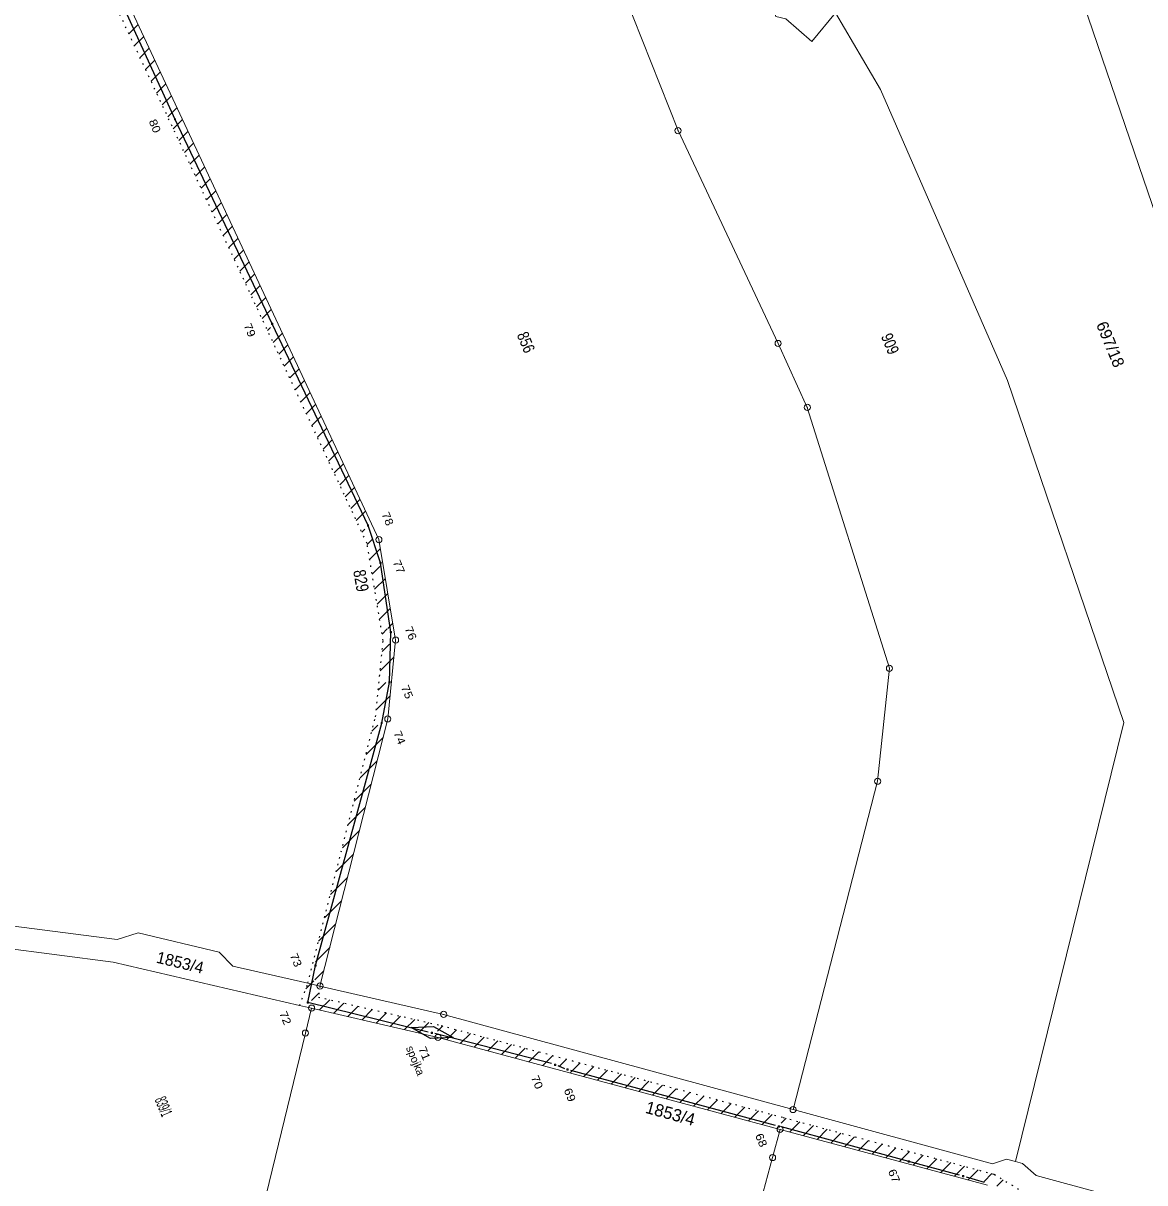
# Model space of a CAD drawing. Extents: x -687415 to -686486, y -959539 to -958099.
# Drawn here: x -686991 to -686717.8, y -959271.3 to -958988.8 of the extents above; entities that cross this region are included whole.
import ezdxf
from ezdxf.enums import TextEntityAlignment as Align

# ---------------------------------------------------------------- set-up
doc = ezdxf.new("R2010")
doc.units = 0
doc.header["$LTSCALE"] = 1.1
doc.linetypes.add('DOTTED', pattern=[1.5, 0.3, -1.2])
for name, color, linetype, lineweight in [('1', 7, 'Continuous', 13), ('2', 7, 'Continuous', 25), ('3', 7, 'Continuous', 13)]:
    doc.layers.add(name, color=color, linetype=linetype, lineweight=lineweight)

msp = doc.modelspace()

# ---------------------------------------------------------------- linework, layer by layer
at = {"layer": '1', "linetype": 'DOTTED', "lineweight": 25}
for p, q in [((-686907.24, -959115.56), (-686968.42, -958984.64)), ((-686921.64, -959222.72), (-686905.15, -959157.8)), ((-686923.68, -959228.09), (-686921.64, -959222.72))]:
    msp.add_line(p, q, dxfattribs=at)
at = {"layer": '1'}
for p, q in [((-686923.68, -959228.09), (-686920.76, -959228.77)), ((-686806.61, -959258.31), (-686756.11, -959271.89))]:
    msp.add_line(p, q, dxfattribs=at)
for points in [[(-686815.11, -958834.64), (-686805.51, -958854.31), (-686782.73, -958855.23), (-686777.25, -958855.45), (-686769.17, -958878.16), (-686758.67, -958907.68), (-686744.98, -958948.05), (-686719.22, -959023.5), (-686699.65, -959080.73), (-686683.05, -959115.22), (-686652.59, -959178.05), (-686618.25, -959249.24), (-686597.25, -959289.88), (-686633.86, -959286.61), (-686711.27, -959277.22), (-686727.83, -959274.04), (-686744.23, -959269.58), (-686747.57, -959266.6), (-686749.25, -959266.14)], [(-686890.94, -958843.77), (-686860.7, -958840.13), (-686859.87, -958843.5), (-686839.25, -958887.41), (-686807.64, -958987.21), (-686805.21, -958987.76), (-686798.91, -958993.27), (-686793.12, -958986.35), (-686782.13, -959004.96), (-686751.25, -959075.9), (-686722.86, -959159.17), (-686749.25, -959266.14)], [(-686970.07, -958962.96), (-686957.75, -958981.41), (-686965.66, -958983.46), (-686904.35, -959114.65)], [(-686844.58, -958981.76), (-686831.48, -959015.02), (-686807.1, -959066.85), (-686799.98, -959082.42), (-686779.98, -959145.99)], [(-686904.35, -959114.65), (-686900.3, -959139.13), (-686902.2, -959158.32), (-686918.72, -959223.39)], [(-686779.98, -959145.99), (-686782.85, -959173.5), (-686803.44, -959253.47)], [(-686921.64, -959222.72), (-686939.9, -959218.53), (-686943.3, -959215.1), (-686962.99, -959210.39), (-686968.12, -959212.05), (-686996.45, -959208.38), (-687006.2, -959208.87)], [(-687007.06, -959214.49), (-686996.53, -959213.97), (-686969.1, -959217.56), (-686923.68, -959228.09)], [(-686803.44, -959253.47), (-686888.58, -959230.3), (-686918.72, -959223.39)], [(-686920.76, -959228.77), (-686922.24, -959234.86), (-686986.17, -959497.52)], [(-686920.76, -959228.77), (-686889.94, -959235.91), (-686806.61, -959258.31), (-686808.46, -959265.16), (-686838.63, -959377.05), (-686887.06, -959538.48)], [(-686749.25, -959266.14), (-686751.43, -959265.55), (-686754.85, -959266.69), (-686803.44, -959253.47)]]:
    msp.add_lwpolyline(points, dxfattribs=at)
for points in [[(-686954.18, -959012.42), (-686954.18, -959012.12), (-686953.88, -959012.12), (-686953.88, -959012.42)], [(-686930.48, -959062.22), (-686930.48, -959061.92), (-686930.18, -959061.92), (-686930.18, -959062.22)], [(-686907.16, -959111.38), (-686907.16, -959111.08), (-686906.86, -959111.08), (-686906.86, -959111.38)], [(-686904.12, -959120.46), (-686904.12, -959120.16), (-686903.82, -959120.16), (-686903.82, -959120.46)], [(-686901.61, -959137.32), (-686901.61, -959137.02), (-686901.31, -959137.02), (-686901.31, -959137.32)], [(-686901.95, -959149.5), (-686901.95, -959149.2), (-686901.65, -959149.2), (-686901.65, -959149.5)], [(-686903.83, -959159.47), (-686903.83, -959159.17), (-686903.53, -959159.17), (-686903.53, -959159.47)], [(-686919.94, -959218.54), (-686919.94, -959218.24), (-686919.64, -959218.24), (-686919.64, -959218.54)], [(-686921.81, -959227.54), (-686921.81, -959227.24), (-686921.51, -959227.24), (-686921.51, -959227.54)], [(-686891.632, -959234.958), (-686891.632, -959234.658), (-686891.332, -959234.658), (-686891.332, -959234.958)], [(-686861.56, -959242.71), (-686861.56, -959242.41), (-686861.26, -959242.41), (-686861.26, -959242.71)], [(-686858.533, -959243.87), (-686858.533, -959243.57), (-686858.233, -959243.57), (-686858.233, -959243.87)], [(-686807.076, -959257.739), (-686807.076, -959257.439), (-686806.776, -959257.439), (-686806.776, -959257.739)], [(-686775.41, -959266.27), (-686775.41, -959265.97), (-686775.11, -959265.97), (-686775.11, -959266.27)], [(-686762.138, -959269.85), (-686762.138, -959269.55), (-686761.838, -959269.55), (-686761.838, -959269.85)]]:
    msp.add_lwpolyline(points, close=True, dxfattribs=at)
at = {"layer": '1', "linetype": 'DOTTED', "lineweight": 25}
for points in [[(-686905.15, -959157.8), (-686903.33, -959139.21), (-686907.24, -959115.56)], [(-686918.72, -959223.39), (-686919.1, -959226.08), (-686889.21, -959233), (-686805.83, -959255.41), (-686754.43, -959269.25), (-686745.48, -959274.75)]]:
    msp.add_lwpolyline(points, dxfattribs=at)
at = {"layer": '1', "lineweight": 25}
msp.add_lwpolyline([(-686896.505, -959233.514), (-686891.049, -959233.281), (-686886.295, -959235.965), (-686891.75, -959236.198)], close=True, dxfattribs=at)
at = {"layer": '1'}
for centre, radius in [((-686831.48, -959015.02), 0.75), ((-686831.48, -959015.02), 0.015), ((-686807.1, -959066.85), 0.75), ((-686807.1, -959066.85), 0.015), ((-686799.98, -959082.42), 0.75), ((-686799.98, -959082.42), 0.015), ((-686904.35, -959114.65), 0.75), ((-686904.35, -959114.65), 0.015), ((-686900.3, -959139.13), 0.75), ((-686900.3, -959139.13), 0.015), ((-686779.98, -959145.99), 0.75), ((-686779.98, -959145.99), 0.015), ((-686902.2, -959158.32), 0.75), ((-686902.2, -959158.32), 0.015), ((-686782.85, -959173.5), 0.75), ((-686782.85, -959173.5), 0.015), ((-686918.72, -959223.39), 0.75), ((-686918.72, -959223.39), 0.015), ((-686920.76, -959228.77), 0.75), ((-686920.76, -959228.77), 0.015), ((-686888.58, -959230.3), 0.75), ((-686888.58, -959230.3), 0.015), ((-686922.24, -959234.86), 0.75), ((-686922.24, -959234.86), 0.015), ((-686889.94, -959235.91), 0.75), ((-686889.94, -959235.91), 0.015), ((-686803.44, -959253.47), 0.75), ((-686803.44, -959253.47), 0.015), ((-686806.61, -959258.31), 0.75), ((-686806.61, -959258.31), 0.015), ((-686808.46, -959265.16), 0.75), ((-686808.46, -959265.16), 0.015)]:
    msp.add_circle(centre, radius, dxfattribs=at)
at = {"layer": '2', "lineweight": 13}
msp.add_line((-686918.72, -959223.39), (-686921.64, -959222.72), dxfattribs=at)
at = {"layer": '2'}
for p, q in [((-686862.295, -959242.281), (-686890.719, -959234.991)), ((-686859.066, -959243.535), (-686860.671, -959242.807)), ((-686807.704, -959257.358), (-686857.599, -959243.941)), ((-686756.823, -959271.237), (-686761.177, -959269.978))]:
    msp.add_line(p, q, dxfattribs=at)
for points in [[(-686892.32, -959234.647), (-686921.66, -959227.39), (-686919.79, -959218.39), (-686903.68, -959159.32), (-686901.8, -959149.35), (-686901.46, -959137.17), (-686903.97, -959120.31), (-686907.01, -959111.23), (-686930.33, -959062.07), (-686954.03, -959012.27), (-686967.47, -958982.75), (-686974.24, -958965.45), (-686981.42, -958939.69), (-686996.08, -958887.99), (-687008.875, -958867.027)], [(-686762.927, -959269.423), (-686775.26, -959266.12), (-686806.285, -959257.697)]]:
    msp.add_lwpolyline(points, dxfattribs=at)
at = {"layer": '3'}
for p, q in [((-686965.253, -958991.416), (-686962.996, -958989.16)), ((-686963.901, -958994.308), (-686961.644, -958992.051)), ((-686962.55, -958997.199), (-686960.293, -958994.942)), ((-686961.199, -959000.091), (-686958.942, -958997.834)), ((-686959.848, -959002.982), (-686957.591, -959000.725)), ((-686958.497, -959005.874), (-686956.239, -959003.616)), ((-686957.145, -959008.765), (-686954.888, -959006.508)), ((-686955.794, -959011.657), (-686953.537, -959009.399)), ((-686954.443, -959014.548), (-686952.186, -959012.291)), ((-686953.092, -959017.439), (-686950.834, -959015.182)), ((-686951.741, -959020.331), (-686949.483, -959018.073)), ((-686950.389, -959023.222), (-686948.132, -959020.965)), ((-686949.038, -959026.114), (-686946.781, -959023.856)), ((-686947.687, -959029.005), (-686945.429, -959026.748)), ((-686946.336, -959031.897), (-686944.078, -959029.639)), ((-686944.985, -959034.788), (-686942.727, -959032.53)), ((-686943.633, -959037.68), (-686941.376, -959035.422)), ((-686942.282, -959040.571), (-686940.024, -959038.313)), ((-686940.931, -959043.462), (-686938.673, -959041.205)), ((-686939.58, -959046.354), (-686937.322, -959044.096)), ((-686938.229, -959049.245), (-686935.971, -959046.987)), ((-686936.877, -959052.137), (-686934.619, -959049.879)), ((-686935.526, -959055.028), (-686933.268, -959052.77)), ((-686934.175, -959057.92), (-686931.917, -959055.661)), ((-686932.824, -959060.811), (-686930.566, -959058.553)), ((-686931.473, -959063.703), (-686930.74, -959062.97)), ((-686930.121, -959066.594), (-686927.863, -959064.336)), ((-686928.77, -959069.485), (-686926.512, -959067.227)), ((-686927.419, -959072.377), (-686925.161, -959070.118)), ((-686926.068, -959075.268), (-686923.809, -959073.01)), ((-686924.717, -959078.16), (-686922.458, -959075.901)), ((-686923.366, -959081.051), (-686921.107, -959078.793)), ((-686922.014, -959083.943), (-686919.756, -959081.684)), ((-686920.663, -959086.834), (-686918.404, -959084.575)), ((-686919.312, -959089.726), (-686917.053, -959087.467)), ((-686917.961, -959092.617), (-686915.702, -959090.358)), ((-686916.61, -959095.508), (-686914.351, -959093.249)), ((-686915.258, -959098.4), (-686912.999, -959096.141)), ((-686913.907, -959101.291), (-686911.648, -959099.032)), ((-686912.556, -959104.183), (-686910.297, -959101.924)), ((-686911.205, -959107.074), (-686908.946, -959104.815)), ((-686909.854, -959109.966), (-686907.594, -959107.706)), ((-686908.502, -959112.857), (-686907.775, -959112.13)), ((-686907.2, -959115.798), (-686905.85, -959114.447)), ((-686906.598, -959119.438), (-686903.989, -959116.829)), ((-686905.996, -959123.079), (-686904.127, -959121.21)), ((-686905.394, -959126.72), (-686902.784, -959124.11)), ((-686904.792, -959130.36), (-686902.182, -959127.75)), ((-686904.191, -959134.001), (-686901.58, -959131.39)), ((-686903.589, -959137.642), (-686902.36, -959136.413)), ((-686902.216, -959136.27), (-686900.978, -959135.031)), ((-686903.592, -959141.888), (-686901.8, -959140.095)), ((-686904.052, -959146.591), (-686900.707, -959143.246)), ((-686904.513, -959151.294), (-686902.7, -959149.481)), ((-686904.973, -959155.997), (-686901.639, -959152.663)), ((-686906.04, -959161.307), (-686904.58, -959159.846)), ((-686907.485, -959166.994), (-686903.353, -959162.862)), ((-686908.93, -959172.681), (-686904.796, -959168.548)), ((-686910.374, -959178.369), (-686906.24, -959174.234)), ((-686911.819, -959184.056), (-686907.684, -959179.921)), ((-686913.263, -959189.743), (-686909.127, -959185.607)), ((-686914.708, -959195.43), (-686910.571, -959191.293)), ((-686916.152, -959201.117), (-686912.015, -959196.979)), ((-686917.597, -959206.805), (-686913.458, -959202.666)), ((-686919.042, -959212.492), (-686914.902, -959208.352)), ((-686919.797, -959217.49), (-686916.345, -959214.038)), ((-686919.955, -959221.891), (-686917.789, -959219.725)), ((-686922.164, -959224.099), (-686920.22, -959222.155)), ((-686920.76, -959226.938), (-686918.968, -959225.146)), ((-686918.802, -959229.223), (-686916.306, -959226.726)), ((-686915.358, -959230.021), (-686912.861, -959227.524)), ((-686911.913, -959230.819), (-686909.415, -959228.322)), ((-686908.468, -959231.617), (-686905.97, -959229.119)), ((-686905.024, -959232.415), (-686902.525, -959229.917)), ((-686901.579, -959233.213), (-686899.08, -959230.714)), ((-686898.134, -959234.011), (-686895.635, -959231.512)), ((-686894.69, -959234.809), (-686892.19, -959232.309)), ((-686890.049, -959234.411), (-686888.759, -959233.121)), ((-686887.863, -959236.468), (-686885.415, -959234.019)), ((-686884.519, -959237.367), (-686882.071, -959234.918)), ((-686881.176, -959238.265), (-686878.727, -959235.817)), ((-686877.832, -959239.164), (-686875.383, -959236.716)), ((-686874.488, -959240.063), (-686872.039, -959237.614)), ((-686871.144, -959240.962), (-686868.695, -959238.513)), ((-686867.8, -959241.861), (-686865.351, -959239.412)), ((-686864.457, -959242.76), (-686862.008, -959240.311)), ((-686860.51, -959243.055), (-686858.664, -959241.209)), ((-686857.66, -959244.448), (-686855.32, -959242.108)), ((-686854.425, -959245.456), (-686851.976, -959243.007)), ((-686851.081, -959246.355), (-686848.632, -959243.906)), ((-686847.738, -959247.254), (-686845.288, -959244.804)), ((-686844.394, -959248.153), (-686841.944, -959245.703)), ((-686841.05, -959249.052), (-686838.6, -959246.602)), ((-686837.706, -959249.95), (-686835.256, -959247.5)), ((-686834.362, -959250.849), (-686831.912, -959248.399)), ((-686831.019, -959251.748), (-686828.569, -959249.298)), ((-686827.675, -959252.647), (-686825.225, -959250.197)), ((-686824.331, -959253.546), (-686821.881, -959251.095)), ((-686820.987, -959254.445), (-686818.537, -959251.994)), ((-686817.643, -959255.343), (-686815.193, -959252.893)), ((-686814.3, -959256.242), (-686811.849, -959253.792)), ((-686810.956, -959257.141), (-686808.505, -959254.69)), ((-686806.383, -959256.811), (-686805.161, -959255.589)), ((-686804.268, -959258.939), (-686801.819, -959256.489)), ((-686800.925, -959259.838), (-686798.476, -959257.389)), ((-686797.581, -959260.737), (-686795.134, -959258.289)), ((-686794.238, -959261.636), (-686791.791, -959259.19)), ((-686790.894, -959262.535), (-686788.448, -959260.09)), ((-686787.551, -959263.435), (-686785.106, -959260.99)), ((-686784.207, -959264.334), (-686781.763, -959261.89)), ((-686780.864, -959265.233), (-686778.421, -959262.79)), ((-686777.52, -959266.132), (-686775.078, -959263.69)), ((-686774.177, -959267.031), (-686771.735, -959264.59)), ((-686770.833, -959267.93), (-686768.393, -959265.49)), ((-686767.49, -959268.829), (-686765.05, -959266.39)), ((-686764.146, -959269.728), (-686761.708, -959267.29)), ((-686760.803, -959270.627), (-686758.365, -959268.19)), ((-686756.922, -959270.99), (-686755.022, -959269.09)), ((-686753.789, -959272.1), (-686752.268, -959270.578))]:
    msp.add_line(p, q, dxfattribs=at)

# ---------------------------------------------------------------- texts
at = {"layer": '1'}
for s, height, rotation, width, p in [('80', 1.95, 292.5, 1.15, (-686960.467, -959012.718)), ('79', 1.95, 292.5, 1.15, (-686937.348, -959062.442)), ('78', 1.95, 292.5, 1.15, (-686903.754, -959108.4)), ('77', 1.95, 292.5, 1.15, (-686901.027, -959120.092)), ('829', 3, 279.9, 0.8, (-686910.635, -959122.26)), ('76', 1.95, 292.5, 1.15, (-686898.136, -959136.263)), ('75', 1.95, 292.5, 1.15, (-686899.006, -959150.58)), ('74', 1.95, 292.5, 1.15, (-686900.848, -959161.711)), ('73', 1.95, 292.5, 1.15, (-686926.098, -959215.888)), ('72', 1.95, 292.5, 1.15, (-686928.689, -959229.998)), ('71', 1.95, 292.5, 1.15, (-686894.795, -959238.616)), ('70', 1.95, 292.5, 1.15, (-686867.351, -959245.632)), ('69', 1.95, 292.5, 1.15, (-686859.37, -959248.729)), ('68', 1.95, 292.5, 1.15, (-686812.744, -959259.762)), ('67', 1.95, 292.5, 1.15, (-686780.377, -959268.479))]:
    msp.add_text(s, height=height, rotation=rotation, dxfattribs=dict(at, width=width)).set_placement(p)
for s, rotation, p in [('697/18', 292.5, (-686727.448, -959067.614)), ('1853/4', 346.5, (-686953.1, -959219.027))]:
    msp.add_text(s, height=2.85, rotation=rotation, dxfattribs=at).set_placement(p, align=Align.CENTER)
for s, width, p in [('856', 0.8, (-686869.827, -959067.115)), ('909', 0.8, (-686781.113, -959067.486)), ('839/1', 0.5, (-686958.118, -959253.279))]:
    msp.add_text(s, height=2.85, rotation=292.5, dxfattribs=dict(at, width=width)).set_placement(p, align=Align.CENTER)
for s, height, rotation, p in [('spojka', 1.95, 292.5, (-686897.811, -959238.439)), ('1853/4', 3, 344.7, (-686839.652, -959254.244))]:
    msp.add_text(s, height=height, rotation=rotation, dxfattribs=at).set_placement(p)

doc.saveas('drawing.dxf')
